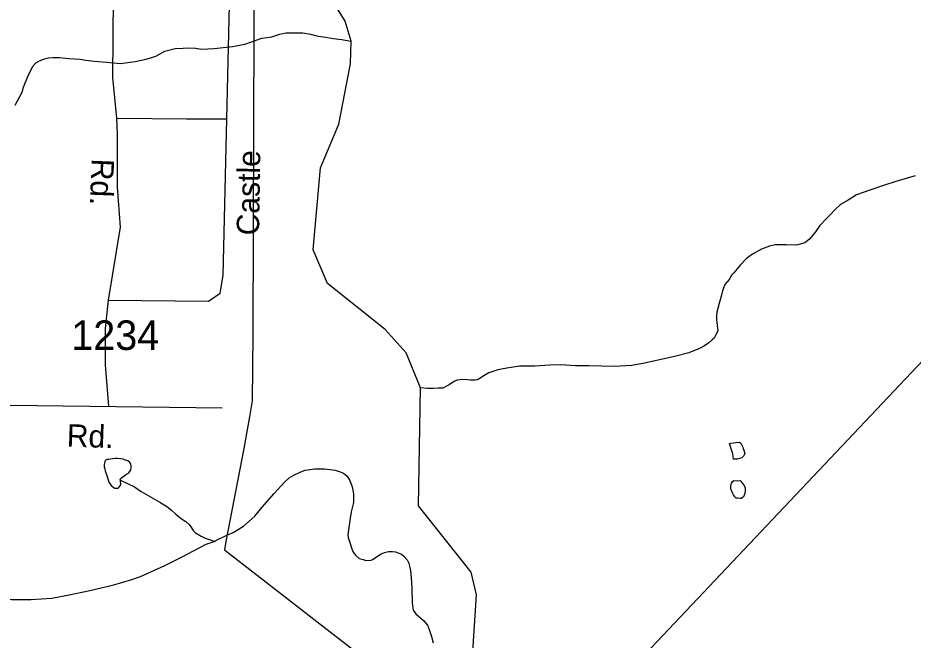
# Model space of a CAD drawing. Extents: x 2056842 to 2160602, y 826753 to 1016856.
# Drawn here: x 2066259 to 2070045, y 854191 to 856821 of the extents above; entities that cross this region are included whole.
import ezdxf

# ---------------------------------------------------------------- set-up
doc = ezdxf.new("R2010")
doc.units = 0
for name, color, linetype in [('Exist Boundary Political City Limit New', 7, 'Continuous'), ('Exist Hydrographic Creek Single Shore', 7, 'Continuous'), ('Exist Hydrographic Misc Water Feature', 7, 'Continuous'), ('Exist Road Non-System Type 51', 7, 'Continuous'), ('Exist Road Non-System Type 51 Label', 7, 'Continuous'), ('Exist Road Secondary Type 51 Attributed', 7, 'Continuous'), ('Exist Road Secondary Type 51 Label', 7, 'Continuous'), ('Exist Road Secondary Type 51 Number Label', 7, 'Continuous'), ('Exist Utilities Gas Line', 7, 'Continuous'), ('Map Preparation Boundary City Limit Buffer Line', 7, 'Continuous')]:
    doc.layers.add(name, color=color, linetype=linetype)

msp = doc.modelspace()

# ---------------------------------------------------------------- linework, layer by layer
at = {"layer": 'Exist Boundary Political City Limit New'}
msp.add_lwpolyline([(2067259.8, 857659.2), (2067253, 855485.2), (2067252.4, 855483.1), (2067250, 855202.5), (2067239.5, 855143.2), (2067214.2, 855000), (2067138.2, 854606.9), (2067132, 854572.3), (2067673.5, 854152.8)], dxfattribs=at)
at = {"layer": 'Exist Hydrographic Creek Single Shore'}
for points in [[(2068178.4, 854076.7), (2068197.6, 854381.3), (2068175.9, 854477.3), (2067952.5, 854757.6), (2067961.5, 855257.5), (2067900.4, 855405.1), (2067812.1, 855503.9), (2067567.7, 855697.8), (2067507.6, 855841.2), (2067538.3, 856186.8), (2067615.4, 856372.4), (2067664.9, 856627.2), (2067668.3, 856722.6), (2067643.2, 856807.6), (2067589.5, 856893.4)], [(2070053.1, 856153.1), (2070029.1, 856147), (2069971.3, 856129), (2069919.4, 856112.6), (2069861.1, 856092.6), (2069805.6, 856072.6), (2069769.7, 856050.5), (2069737.7, 856032.6), (2069713.5, 856010.3), (2069695.9, 855990.2), (2069679.7, 855974.4), (2069649.9, 855944), (2069632.1, 855916.3), (2069605.9, 855886.2), (2069586.2, 855870.1), (2069551.7, 855860.3), (2069507.8, 855862.1), (2069461.9, 855861.8), (2069437.9, 855855.7), (2069403.7, 855843.8), (2069365.9, 855821.6), (2069340.1, 855803.6), (2069312.2, 855773.7), (2069300.1, 855759.8), (2069286.4, 855743.6), (2069278.2, 855735.5), (2069266.3, 855715.8), (2069248.2, 855693.4), (2069238.4, 855667.7), (2069234.5, 855649.6), (2069226.5, 855619.5), (2069214.4, 855577.6), (2069212.6, 855561.6), (2069212.6, 855543.4), (2069214.6, 855535.3), (2069216.7, 855519.6), (2069218.3, 855501.5), (2069216.7, 855491.6), (2069210.7, 855481.5), (2069202.9, 855467.3), (2069194.7, 855459.6), (2069180.8, 855447.6), (2069162.7, 855435.3), (2069140.8, 855423.6), (2069096.9, 855405.1), (2069040.7, 855391.3), (2068978.8, 855377.2), (2068908.9, 855361), (2068855, 855350.9), (2068780.7, 855346.7), (2068673.1, 855350.5), (2068616.9, 855350.5), (2068574.8, 855352.4), (2068553.1, 855354.5), (2068508.8, 855352.3), (2068444.8, 855348.2), (2068380.7, 855348.2), (2068327.1, 855340.1), (2068289, 855333.7), (2068251.1, 855319.9), (2068229.1, 855307.9), (2068209.2, 855295.5), (2068203.1, 855291.5), (2068192.8, 855289.8), (2068171.1, 855289.5), (2068151.2, 855291.7), (2068129.1, 855291.4), (2068117.2, 855289.5), (2068107.1, 855285.4), (2068093.2, 855277.4), (2068083.3, 855269.5), (2068056.1, 855256.2), (2068035.7, 855256.2), (2068015.2, 855253.7), (2067990.9, 855253.7), (2067961.5, 855257.5)], [(2067088.2, 854607.7), (2067096.6, 854611.7), (2067142.4, 854633.6), (2067168.6, 854645.8), (2067212.5, 854672), (2067260.3, 854713.9), (2067292, 854752.1), (2067342.1, 854810.2), (2067386, 854858.3), (2067405.8, 854876.4), (2067426.1, 854888.3), (2067455.7, 854902.1), (2067474.1, 854908.3), (2067513.7, 854914.4), (2067555.9, 854914.5), (2067600, 854908.6), (2067621.8, 854902.5), (2067635.7, 854896.7), (2067649.9, 854884.8), (2067662, 854864.8), (2067672, 854838.9), (2067678.2, 854808.8), (2067678, 854772.6), (2067667.9, 854732.8), (2067664, 854706.6), (2067656.6, 854656.6), (2067654.6, 854636.6), (2067656.2, 854624.6), (2067662.4, 854602.6), (2067670.4, 854576.6), (2067676.5, 854562.7), (2067688.6, 854548.7), (2067702.6, 854534.8), (2067718.6, 854530.8), (2067730.6, 854526.9), (2067752.6, 854528.9), (2067758.3, 854530.8), (2067794.6, 854554.9), (2067808.6, 854561), (2067826.6, 854565.1), (2067842.4, 854565.2), (2067856.3, 854563), (2067880.7, 854553.2), (2067890.4, 854545.3), (2067904.7, 854529.3), (2067912.5, 854515.1), (2067918.7, 854485.4), (2067922.6, 854453.2), (2067925, 854411.4), (2067926.7, 854347.5), (2067931, 854317.2), (2067941.2, 854301.4), (2067974.7, 854273.2), (2067990.9, 854253.3), (2067999.3, 854231.3), (2068007.3, 854205.4), (2068015.3, 854179.4)], [(2066036.7, 854399.9), (2066083.1, 854391.7), (2066147, 854375.9), (2066231.1, 854362), (2066315.2, 854362.2), (2066402.9, 854368.4), (2066469.2, 854380.6), (2066563.1, 854400.9), (2066664.8, 854424.8), (2066740.7, 854447), (2066776.7, 854459), (2066880.9, 854505.2), (2066950.6, 854541.3), (2067054.4, 854595.8), (2067088.2, 854607.7)]]:
    msp.add_lwpolyline(points, dxfattribs=at)
at = {"layer": 'Exist Hydrographic Misc Water Feature'}
for points in [[(2066247.3, 856452), (2066277, 856507.9), (2066283, 856528.1), (2066303.1, 856579.9), (2066323, 856618.3), (2066334.7, 856631.9), (2066346.8, 856638.1), (2066366.8, 856646.1), (2066388.6, 856652.1), (2066406.8, 856654.2), (2066434.9, 856654.4), (2066474.9, 856650.3), (2066522.7, 856646.3), (2066546.7, 856642.3), (2066580.9, 856638.3), (2066634.6, 856634.7), (2066692.7, 856628.7), (2066754.8, 856636.7), (2066800.7, 856646.8), (2066842.8, 856659.1), (2066880.7, 856680.9), (2066924.6, 856691.3), (2066957.5, 856693.7), (2066976.7, 856695), (2067010, 856693.7), (2067035.5, 856688.6), (2067089.3, 856692.4), (2067166, 856700.1), (2067218.5, 856710.4), (2067290.6, 856735.6), (2067332.4, 856741.8), (2067366.5, 856752.1), (2067392.5, 856757.9), (2067464.5, 856758.4), (2067496.5, 856752.3), (2067528.3, 856744.2), (2067560.9, 856740.1), (2067592.6, 856734.5), (2067628.5, 856730.6), (2067658.5, 856724.5), (2067668.3, 856722.6)], [(2069316.5, 855023.7), (2069324.5, 855005.8), (2069326.6, 854999.9), (2069328.6, 854993.9), (2069332.3, 854984), (2069332.5, 854979.9), (2069326.8, 854967.8), (2069320.6, 854961.8), (2069310.6, 854958.1), (2069300.5, 854955.9), (2069288.6, 854955.7), (2069284.7, 854955.9), (2069282.5, 854977.8), (2069274.5, 855003.7), (2069270.6, 855013.6), (2069268.5, 855021.6), (2069274.5, 855023.6), (2069294.8, 855025.8), (2069310.4, 855027.9), (2069316.5, 855023.7)], [(2066692.1, 854867), (2066691.9, 854871.1), (2066696.4, 854876.9), (2066702.1, 854880.9), (2066714, 854888.8), (2066725.9, 854896.7), (2066732, 854903.1), (2066735.9, 854911), (2066738.2, 854918.8), (2066737.8, 854927), (2066736.1, 854935), (2066732, 854940.9), (2066724, 854949), (2066709.7, 854952.8), (2066703.7, 854954.9), (2066693.9, 854956.8), (2066679.8, 854958.9), (2066669.9, 854958.8), (2066658.2, 854956.9), (2066643.9, 854954.7), (2066635.7, 854954.7), (2066629.9, 854950.7), (2066626, 854944.8), (2066624, 854932.9), (2066624, 854922.8), (2066626, 854914.7), (2066627.7, 854906.8), (2066636.1, 854882.8), (2066644.1, 854858.9), (2066648.2, 854853), (2066653.9, 854844.8), (2066662.1, 854837.1), (2066668.1, 854832.9), (2066676.3, 854832.9), (2066682.2, 854832.8), (2066685.9, 854835.1), (2066689.8, 854841), (2066692.3, 854845.1), (2066694.1, 854848.8), (2066692.3, 854862.9), (2066692.1, 854867)], [(2066692.1, 854867), (2066722, 854853.1), (2066751.9, 854838.9), (2066780.2, 854819.1), (2066810.4, 854801.2), (2066858.4, 854773.2), (2066888.1, 854755.3), (2066908.4, 854739.3), (2066926.2, 854723.6), (2066950.4, 854703.3), (2066968.5, 854691.6), (2066982.6, 854679.3), (2066990.2, 854669.6), (2067000.3, 854653.5), (2067010.5, 854643.4), (2067034.5, 854629.6), (2067050.7, 854621.5), (2067080.4, 854611.7), (2067088.2, 854607.7)], [(2069318.8, 854858.7), (2069322.9, 854852.8), (2069330.5, 854844.8), (2069332.6, 854836.8), (2069334.8, 854832.8), (2069334.8, 854826.7), (2069334.8, 854822.7), (2069333, 854810.8), (2069330.7, 854802.6), (2069326.8, 854796.7), (2069323.1, 854792.8), (2069317, 854788.8), (2069312.7, 854788.7), (2069302.8, 854790.6), (2069296.9, 854790.7), (2069290.5, 854796.5), (2069284.8, 854804.7), (2069280.5, 854812.6), (2069276.6, 854822.5), (2069274.5, 854830.5), (2069274.5, 854840.7), (2069274.7, 854848.8), (2069277, 854854.5), (2069280.5, 854860.5), (2069286.6, 854864.8), (2069302.8, 854864.4), (2069312.7, 854864.6), (2069317, 854862.7), (2069318.8, 854858.7)]]:
    msp.add_lwpolyline(points, dxfattribs=at)
at = {"layer": 'Exist Road Non-System Type 51'}
for points in [[(2066676.6, 856397.2), (2066661, 856568.7), (2066663.1, 856911.6), (2066651.7, 857396.9)], [(2067142.9, 856394.1), (2067153.3, 856878.4), (2067158.5, 857376.1)], [(2066641.3, 855628.2), (2066693.2, 855935.8), (2066680.7, 856106.2), (2066680.7, 856328.6), (2066676.6, 856397.2)], [(2066641.3, 855628.2), (2067065, 855624), (2067114.8, 855657.3), (2067127.3, 855732.1), (2067142.9, 856394.1)], [(2066676.6, 856397.2), (2066971.5, 856395.1), (2067142.9, 856394.1)], [(2066643.3, 855179.4), (2066628.8, 855353.8), (2066628.8, 855507.6), (2066641.3, 855628.2)]]:
    msp.add_lwpolyline(points, dxfattribs=at)
at = {"layer": 'Exist Road Secondary Type 51 Attributed'}
msp.add_lwpolyline([(2064936.5, 855014.5), (2065883.4, 854990.6), (2065889.7, 855188.1), (2067122.6, 855172.5)], dxfattribs=at)
at = {"layer": 'Exist Utilities Gas Line'}
msp.add_lwpolyline([(2063216.6, 847084.7), (2065392.1, 849881.8), (2068277.7, 853460.4), (2070574.6, 855889.8)], dxfattribs=at)
at = {"layer": 'Map Preparation Boundary City Limit Buffer Line'}
msp.add_lwpolyline([(2067259.8, 857659.2), (2067253, 855485.2), (2067252.4, 855483.1), (2067250, 855202.5), (2067239.5, 855143.2), (2067214.2, 855000), (2067138.2, 854606.9), (2067132, 854572.3), (2067673.5, 854152.8)], dxfattribs=at)

# ---------------------------------------------------------------- texts
at = {"layer": 'Exist Road Non-System Type 51 Label'}
for s, rotation, p in [('Castle', 89.1345, (2067278.7, 855901.4)), ('Rd.', 267.782, (2066571.2, 856227.6))]:
    msp.add_text(s, height=95, rotation=rotation, dxfattribs=at).set_placement(p)
at = {"layer": 'Exist Road Secondary Type 51 Label'}
msp.add_text('Rd.', height=95, rotation=358.0338, dxfattribs=at).set_placement((2066464.4, 855008.9))
at = {"layer": 'Exist Road Secondary Type 51 Number Label'}
msp.add_text('1234', height=125, dxfattribs=at).set_placement((2066484.7, 855417.2))

doc.saveas('drawing.dxf')
